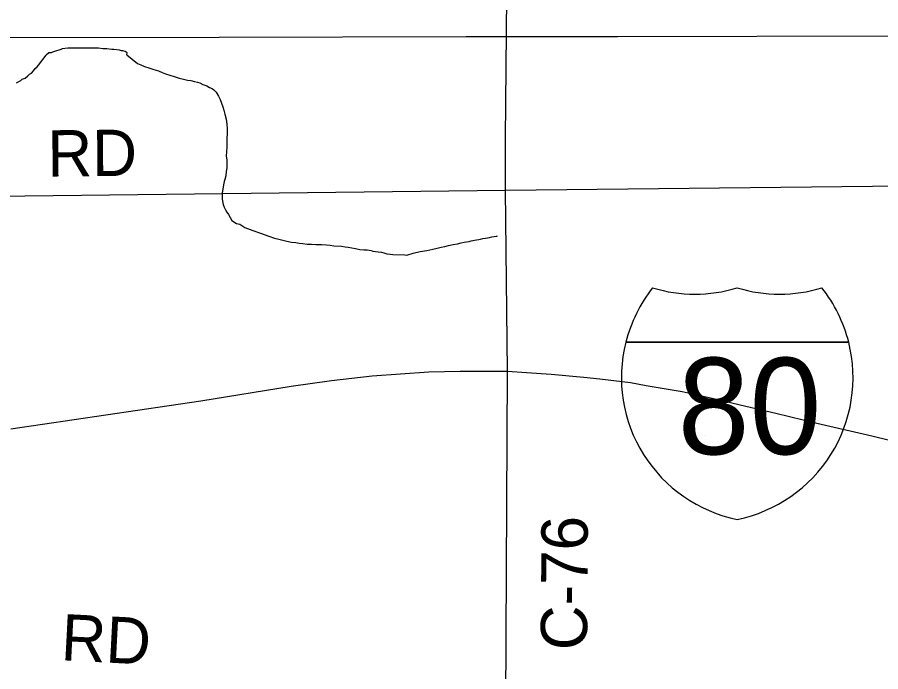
# Model space of a CAD drawing. Extents: x 2010165 to 2382125, y 1060529 to 1407316.
# Drawn here: x 2117943 to 2123534, y 1225981 to 1230221 of the extents above; entities that cross this region are included whole.
import ezdxf

# ---------------------------------------------------------------- set-up
doc = ezdxf.new("R2010")
doc.units = 0
for name, color, linetype in [('GM_X_County_Road', 7, 'Continuous'), ('GM_X_County_Road_Text', 7, 'Continuous'), ('GM_X_Interstate_Location', 7, 'Continuous'), ('GM_X_Interstate_Route', 7, 'Continuous'), ('GM_X_Interstate_Shield', 7, 'Continuous'), ('GM_X_Minor_Lake', 7, 'Continuous'), ('GM_X_Minor_River', 7, 'Continuous'), ('GM_X_Rail_Line', 7, 'Continuous')]:
    doc.layers.add(name, color=color, linetype=linetype)

msp = doc.modelspace()

# ---------------------------------------------------------------- linework, layer by layer
at = {"layer": 'GM_X_County_Road'}
for points in [[(2121105.1, 1229101.1), (2121104.9, 1229434.5), (2121123.1, 1231504.1), (2121126.9, 1233091.7), (2121121.5, 1235043)], [(2121105.1, 1229101.1), (2126848.1, 1229163.7), (2127113.5, 1229166.6), (2127528.7, 1229168.7)], [(2113820.5, 1229023.2), (2113902, 1229035.2), (2114010, 1229037.7), (2114769.6, 1229057), (2115376.1, 1229051.8), (2116890.9, 1229052.1), (2121105.1, 1229101.1)], [(2121107, 1225773.9), (2121117.2, 1227927), (2121105.1, 1229101.1)]]:
    msp.add_lwpolyline(points, dxfattribs=at)
at = {"layer": 'GM_X_Interstate_Route'}
msp.add_lwpolyline([(2117901.3, 1227554.9), (2119131.2, 1227736.7), (2119716.4, 1227829.9), (2119977.1, 1227868), (2120240.5, 1227898.7), (2120608.4, 1227922.8), (2120810.5, 1227928.8), (2121117.2, 1227927), (2121240.1, 1227919.5), (2121399.4, 1227909.5), (2121611, 1227888.9), (2121715.5, 1227878.6), (2121914.6, 1227854.1), (2122014.4, 1227835.2), (2122247.8, 1227796.1), (2122442.1, 1227752.9), (2122660.6, 1227701.6), (2122853.9, 1227656), (2123119.8, 1227590.4), (2123475.5, 1227509.9), (2124443.7, 1227272.2)], dxfattribs=at)
at = {"layer": 'GM_X_Interstate_Shield'}
for p, q in [((2121883.4, 1228116.2), (2123326.2, 1228116.2)), ((2123326.2, 1228116.2), (2121883.4, 1228116.2)), ((2123326.2, 1228116.2), (2121883.4, 1228116.2))]:
    msp.add_line(p, q, dxfattribs=at)
for centre, start, end in [((2122792.3, 1227886.3), 141.669, 165.8066), ((2122330.8, 1229364.4), 253.0091, 286.9909), ((2122878.7, 1229364.4), 253.0091, 286.9909), ((2122417.3, 1227886.3), 14.1934, 38.331), ((2122792.3, 1227886.3), 165.8066, 258.463), ((2122417.3, 1227886.3), 281.537, 14.1934)]:
    msp.add_arc(centre, 937.5, start, end, dxfattribs=at)
at = {"layer": 'GM_X_Minor_Lake'}
msp.add_lwpolyline([(2118653.8, 1229976.8), (2118655, 1229989.6), (2118641.4, 1229998.6), (2118627.8, 1230003.2), (2118618.8, 1230003.2), (2118605.2, 1230007.7), (2118569.1, 1230012.2), (2118564.5, 1230012.2), (2118560, 1230012.2), (2118555.5, 1230012.2), (2118523.9, 1230016.8), (2118519.3, 1230016.8), (2118514.8, 1230016.8), (2118505.8, 1230016.8), (2118496.7, 1230016.8), (2118469.6, 1230021.3), (2118465.1, 1230021.3), (2118456, 1230021.3), (2118447, 1230021.3), (2118438, 1230021.3), (2118428.9, 1230021.3), (2118419.9, 1230021.3), (2118410.8, 1230021.3), (2118406.3, 1230021.3), (2118401.8, 1230021.3), (2118397.3, 1230021.3), (2118392.7, 1230021.3), (2118383.7, 1230021.3), (2118374.7, 1230021.3), (2118365.6, 1230021.3), (2118352.1, 1230021.3), (2118315.9, 1230021.3), (2118306.8, 1230021.3), (2118279.7, 1230021.3), (2118270.7, 1230021.3), (2118234.5, 1230016.8), (2118225.5, 1230012.3), (2118211.9, 1230007.8), (2118198.4, 1230003.2), (2118171.2, 1229994.2), (2118162.2, 1229989.7), (2118157.7, 1229989.7), (2118153.1, 1229989.7), (2118148.6, 1229989.7), (2118130.6, 1229975.7), (2118130, 1229975.7), (2118130, 1229975.7)], dxfattribs=at)
at = {"layer": 'GM_X_Minor_River'}
for points in [[(2117994.1, 1229826.8), (2118011.9, 1229841.1), (2118021.8, 1229851.2), (2118035.7, 1229859.5), (2118049.5, 1229873.7), (2118059.4, 1229887.9), (2118071.2, 1229900.1), (2118081.1, 1229910.3), (2118130, 1229975.7)], [(2118653.8, 1229976.8), (2118722.6, 1229921.7), (2118742.8, 1229912), (2118767, 1229902.3), (2118795.2, 1229892.7), (2118827.4, 1229883.1), (2118857.7, 1229873.5), (2118881.9, 1229863.8), (2118904.1, 1229854.1), (2118930.2, 1229846.5), (2118958.4, 1229836.9), (2118990.7, 1229827.3), (2119018.9, 1229819.7), (2119045, 1229814), (2119067.1, 1229810.3), (2119091.3, 1229804.7), (2119109.4, 1229800.9), (2119125.5, 1229795.1), (2119145.7, 1229785.4), (2119169.9, 1229775.7), (2119188.1, 1229766), (2119204.2, 1229760.2), (2119216.4, 1229750.3), (2119230.6, 1229736.5), (2119247, 1229710.6), (2119257.4, 1229688.7), (2119265.8, 1229664.8), (2119274.1, 1229640.8), (2119280.4, 1229618.8), (2119286.8, 1229592.8), (2119295.3, 1229560.8), (2119299.8, 1229528.8), (2119302.3, 1229498.7), (2119302.7, 1229466.6), (2119301.1, 1229438.5), (2119299.6, 1229404.4), (2119300, 1229378.3), (2119298.4, 1229348.2), (2119296.8, 1229322.1), (2119299.2, 1229294), (2119299.6, 1229267.9), (2119299.9, 1229245.8), (2119296.3, 1229221.7), (2119292.7, 1229193.6), (2119287, 1229169.4), (2119283.2, 1229157.3), (2119281.3, 1229145.2), (2119270.2, 1229082.9), (2119270.5, 1229062.8), (2119270.8, 1229044.7), (2119273, 1229028.7), (2119277.3, 1229008.7), (2119283.6, 1228990.8), (2119291.9, 1228972.8), (2119300.1, 1228958.9), (2119310.3, 1228943), (2119332.9, 1228905.2), (2119363.3, 1228885.6), (2119383.4, 1228879.8), (2119415.8, 1228858.2), (2119468.3, 1228838.9), (2119518.6, 1228821.6), (2119573.1, 1228802.3), (2119609.3, 1228790.8), (2119637.5, 1228783.2), (2119661.7, 1228777.6), (2119687.8, 1228769.9), (2119718, 1228764.3), (2119746.1, 1228760.7), (2119768.2, 1228757), (2119792.3, 1228755.4), (2119820.4, 1228751.8), (2119848.5, 1228750.2), (2119876.6, 1228748.6), (2119912.7, 1228749.1), (2119944.9, 1228745.6), (2119968.9, 1228743.9), (2119993.1, 1228740.3), (2120043.2, 1228737), (2120065.4, 1228733.3), (2120085.4, 1228731.6), (2120133.7, 1228722.2), (2120161.9, 1228716.6), (2120189.9, 1228715.1), (2120208, 1228713.3), (2120222.1, 1228711.5), (2120234.1, 1228709.7), (2120246.2, 1228705.8), (2120262.3, 1228704.1), (2120280.4, 1228700.3), (2120300.5, 1228698.6), (2120316.6, 1228694.8), (2120336.7, 1228689.1), (2120356.8, 1228685.4), (2120374.9, 1228683.6), (2120453.1, 1228680.8), (2120465.2, 1228678.9), (2120507.1, 1228693.6)], [(2117938.4, 1229795.8), (2117954.3, 1229804.1), (2117966.2, 1229810.3), (2117976.1, 1229820.5), (2117994.1, 1229826.8)], [(2120507.1, 1228693.6), (2120551.1, 1228702.3), (2120595.1, 1228708.9), (2120633.1, 1228717.5), (2120661.1, 1228723.9), (2120687, 1228732.4), (2120711, 1228736.7), (2120735, 1228743.1), (2120765, 1228749.6), (2120793, 1228754), (2120816.9, 1228760.3), (2120836.9, 1228764.7), (2120852.9, 1228766.9), (2120868.9, 1228769.1), (2120882.9, 1228773.3), (2120892.9, 1228775.5), (2120902.9, 1228775.7), (2120916.9, 1228779.9), (2120930.9, 1228782.1), (2120942.9, 1228782.3), (2120956.9, 1228786.5), (2120974.9, 1228788.8), (2120988.9, 1228791), (2121000.9, 1228793.1), (2121014.9, 1228797.4), (2121030.9, 1228799.6), (2121044.9, 1228801.8), (2121051, 1228801.9), (2121050.9, 1228803.9)]]:
    msp.add_lwpolyline(points, dxfattribs=at)
at = {"layer": 'GM_X_Rail_Line'}
msp.add_lwpolyline([(2113868.1, 1230085.9), (2119251.5, 1230091.7), (2120849.1, 1230095.5), (2121828.5, 1230096.3), (2123632.9, 1230100.4), (2125920.1, 1230102.1), (2127174.2, 1230104.5), (2129750.1, 1230110.3), (2131919.6, 1230114.4)], dxfattribs=at)

# ---------------------------------------------------------------- texts
at = {"layer": 'GM_X_County_Road_Text'}
for s, rotation, p in [('RD', 0.4936, (2118140.1, 1229188.7)), ('C-76', 89.6571, (2121632.4, 1226119.6)), ('RD', 357.0407, (2118222, 1226055.8))]:
    msp.add_text(s, height=300, rotation=rotation, dxfattribs=at).set_placement(p)
at = {"layer": 'GM_X_Interstate_Location'}
for s in ['-', '.', ',']:
    msp.add_text(s, height=1, dxfattribs=at).set_placement((2122604.6, 1227717.3))
msp.add_text('80', height=1, rotation=0, dxfattribs=at).set_placement((2122400.3, 1227510.3))
at = {"layer": 'GM_X_Interstate_Shield'}
msp.add_text('80', height=625, dxfattribs=at).set_placement((2122219.6, 1227389.7))

doc.saveas('drawing.dxf')
